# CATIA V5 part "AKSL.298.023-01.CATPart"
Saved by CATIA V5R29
Part number: АКСЛ.298.023-01
Material "Steel": density 7860 kg/m3, Young's modulus 2e+11 Pa, Poisson ratio 0.266, thermal expansion 1.17e-05 1/K
Bounding box of the stored display mesh (mm): x -149 to 149, y -52 to 51, z -51 to 52
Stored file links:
  Z:\ООО Аксель\Соединения бруса\Соединения бруса\Соединения из листа\АКСЛ.298.020 (Дуо)\AKSL.298.023-01.CATPart
  Z:\ООО Аксель\Соединения бруса\Соединения бруса\Соединения из листа\АКСЛ.298.020 (Дуо)\AKSL.298.023.CATPart
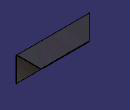
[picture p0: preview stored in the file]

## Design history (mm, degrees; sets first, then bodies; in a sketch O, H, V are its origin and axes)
Set1 "External References"
  DatumSurface1 "Extrude.2": linked copy from another document
  Plane1 "OutputPlane.1 (Line.4)": linked copy from another document
Body1 (main body)
  Body2 "Body from original PartBody"
    Solid1: linked copy from another document
  Assemble1: tool Body2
